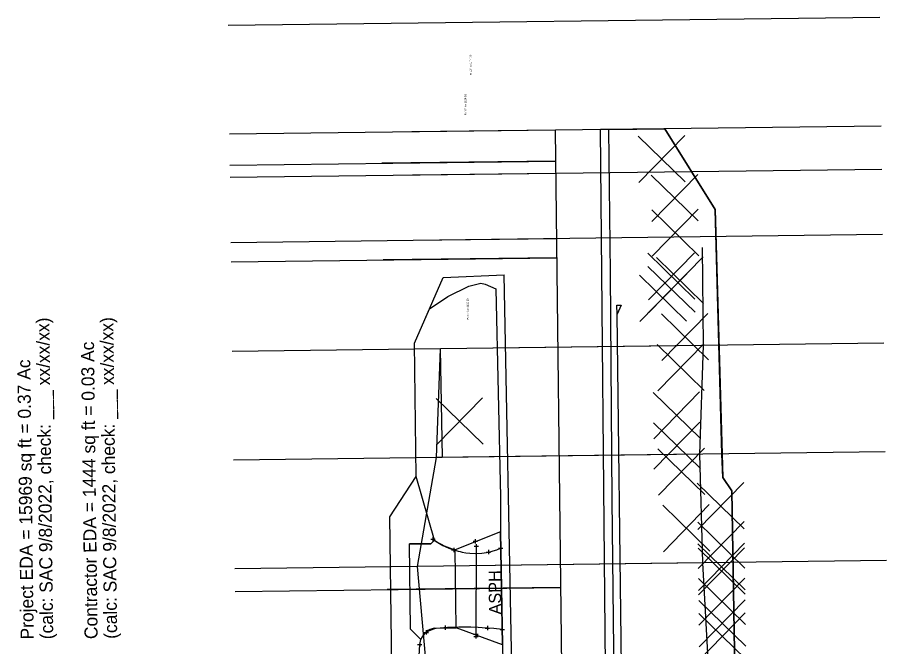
# Model space of a CAD drawing. Extents: x 2341000 to 2341204, y 624110 to 624511.
# Drawn here: x 2341000.5 to 2341200.5, y 624366.6 to 624511.4 of the extents above; entities that cross this region are included whole.
import ezdxf

# ---------------------------------------------------------------- set-up
doc = ezdxf.new("R2010")
doc.units = 0
for name, color, linetype in [('DR_X_Elev_Flow', 7, 'Continuous'), ('DR_X_Storm_Sewer', 7, 'Continuous'), ('GE_P_Driveway_CL', 7, 'Continuous'), ('PV_P_Drive', 7, 'Continuous'), ('PV_X_Text', 7, 'Continuous'), ('RD_P_GR_Rt', 7, 'Continuous'), ('RW_P_Const_Limits', 7, 'Continuous'), ('SC_ProfileRun1', 7, 'Continuous'), ('SC_Scratch1', 7, 'Continuous'), ('SC_Scratch10', 7, 'Continuous'), ('SC_Scratch2', 7, 'Continuous'), ('SC_Scratch4', 7, 'Continuous'), ('SC_Scratch5', 7, 'Continuous'), ('SV_X_Shot_Marker', 7, 'Continuous'), ('VG_P_Cells', 7, 'Continuous')]:
    doc.layers.add(name, color=color, linetype=linetype)

msp = doc.modelspace()

# ---------------------------------------------------------------- linework, layer by layer
at = {"layer": 'DR_X_Elev_Flow'}
for p, q in [((2341106.04, 624390.2), (2341106.04, 624389.2)), ((2341105.54, 624389.7), (2341106.54, 624389.7)), ((2341106.04, 624389.7), (2341106.04, 624389.7)), ((2341105.96, 624369.99), (2341105.96, 624368.99)), ((2341105.46, 624369.49), (2341106.46, 624369.49)), ((2341105.96, 624369.49), (2341105.96, 624369.49))]:
    msp.add_line(p, q, dxfattribs=at)
at = {"layer": 'DR_X_Storm_Sewer'}
for p, q in [((2341106.04, 624389.7), (2341105.96, 624369.49)), ((2341106.04, 624389.7), (2341105.96, 624369.49)), ((2341106.04, 624389.7), (2341106.04, 624389.7)), ((2341105.96, 624369.49), (2341105.96, 624369.49))]:
    msp.add_line(p, q, dxfattribs=at)
at = {"layer": 'GE_P_Driveway_CL'}
msp.add_line((2341125.56, 624380.22), (2341085.56, 624379.72), dxfattribs=at)
at = {"layer": 'PV_P_Drive'}
for p, q in [((2341111.66, 624393.04), (2341101.18, 624388.91)), ((2341111.66, 624393.04), (2341101.18, 624388.91)), ((2341095.6, 624390.28), (2341090.68, 624390.22)), ((2341095.6, 624390.28), (2341090.68, 624390.22)), ((2341090.92, 624370.6), (2341090.68, 624390.22)), ((2341090.92, 624370.6), (2341090.68, 624390.22)), ((2341096.41, 624391.11), (2341095.6, 624390.28)), ((2341096.41, 624391.11), (2341095.6, 624390.28)), ((2341101.4, 624370.92), (2341101.18, 624388.91)), ((2341101.4, 624370.92), (2341101.18, 624388.91)), ((2341093.32, 624368.26), (2341090.92, 624370.6)), ((2341093.32, 624368.26), (2341090.92, 624370.6)), ((2341096.4, 624370.85), (2341101.4, 624370.92)), ((2341096.4, 624370.85), (2341101.4, 624370.92)), ((2341112.12, 624367.05), (2341101.4, 624370.92)), ((2341112.12, 624367.05), (2341101.4, 624370.92))]:
    msp.add_line(p, q, dxfattribs=at)
msp.add_lwpolyline([(2341112.12, 624367.05), (2341111.86, 624380.05), (2341111.66, 624393.04)], dxfattribs=at)
msp.add_lwpolyline([(2341112.12, 624367.05), (2341111.86, 624380.05), (2341111.66, 624393.04)], dxfattribs=at)
for centre, radius, start, end in [((2341104.98, 624403.43), 15, 235.168, 255.3249), ((2341104.98, 624403.43), 15, 235.168, 255.3249), ((2341097.09, 624366.91), 4, 99.9333, 160.2994), ((2341097.09, 624366.91), 4, 99.9333, 160.2994)]:
    msp.add_arc(centre, radius, start, end, dxfattribs=at)
at = {"layer": 'RD_P_GR_Rt'}
for p, q in [((2341138.44, 624445.13), (2341139.44, 624445.14)), ((2341138.46, 624443.13), (2341138.44, 624445.13)), ((2341139.44, 624445.14), (2341138.46, 624443.13)), ((2341140.75, 624255.64), (2341138.46, 624443.13))]:
    msp.add_line(p, q, dxfattribs=at)
at = {"layer": 'RW_P_Const_Limits'}
for p, q in [((2341149.46, 624485.77), (2341134.66, 624485.59)), ((2341135.83, 624358.38), (2341134.66, 624485.59)), ((2341161.03, 624467.15), (2341149.46, 624485.77)), ((2341162.54, 624410.92), (2341161.03, 624467.15)), ((2341114.29, 624358.12), (2341112.45, 624452.18)), ((2341086.19, 624396.46), (2341092.24, 624405.75)), ((2341086.67, 624357.74), (2341086.19, 624396.46))]:
    msp.add_line(p, q, dxfattribs=at)
for points in [[(2341092.24, 624405.75), (2341091.86, 624436.46), (2341098.43, 624451.53), (2341112.45, 624452.18)], [(2341165.58, 624360.98), (2341164.88, 624402.48), (2341162.81, 624405.53), (2341162.54, 624410.92)]]:
    msp.add_lwpolyline(points, dxfattribs=at)
at = {"layer": 'SC_ProfileRun1'}
msp.add_line((2341106.04, 624389.7), (2341105.96, 624369.49), dxfattribs=at)
at = {"layer": 'SC_Scratch1'}
for p, q in [((2341198.95, 624511.38), (2341048.96, 624509.53)), ((2341199.25, 624486.38), (2341049.27, 624484.53)), ((2341049.35, 624477.38), (2341124.35, 624478.3)), ((2341199.38, 624476.38), (2341049.39, 624474.53)), ((2341199.56, 624461.39), (2341049.57, 624459.53)), ((2341049.63, 624455.15), (2341124.62, 624456.08)), ((2341199.87, 624436.39), (2341049.88, 624434.53)), ((2341200.18, 624411.39), (2341050.19, 624409.54)), ((2341200.49, 624386.39), (2341050.5, 624384.54)), ((2341050.57, 624379.29), (2341125.56, 624380.22))]:
    msp.add_line(p, q, dxfattribs=at)
at = {"layer": 'SC_Scratch10'}
for points in [[(2341138.01, 624338.62), (2341137.31, 624400.34), (2341136.96, 624452.62), (2341136.56, 624485.61), (2341149.46, 624485.77), (2341161.03, 624467.15), (2341162.81, 624405.53), (2341164.88, 624402.48), (2341165.58, 624360.98)], [(2341092.56, 624357.81), (2341093.07, 624367.11), (2341093.32, 624368.26), (2341090.92, 624370.6), (2341090.68, 624390.22), (2341095.6, 624390.28), (2341096.41, 624391.11), (2341092.24, 624405.75), (2341091.86, 624436.46), (2341095.32, 624444.36), (2341099.55, 624447.14), (2341104.32, 624449.54), (2341107.09, 624450.21), (2341108.13, 624449.98), (2341110.6, 624448.93), (2341111.64, 624401.06), (2341111.66, 624393.04), (2341112.12, 624367.05), (2341112.63, 624338.3)]]:
    msp.add_lwpolyline(points, dxfattribs=at)
at = {"layer": 'SC_Scratch2'}
for p, q in [((2341124.26, 624485.46), (2341091.26, 624485.05)), ((2341128.28, 624160.48), (2341124.26, 624485.46)), ((2341124.38, 624475.46), (2341091.39, 624475.05)), ((2341124.57, 624460.46), (2341091.57, 624460.05)), ((2341158.38, 624435.87), (2341097.8, 624435.13)), ((2341098.29, 624410.13), (2341097.8, 624435.13)), ((2341157.54, 624410.86), (2341096.91, 624410.11)), ((2341158.21, 624385.87), (2341092.5, 624385.06))]:
    msp.add_line(p, q, dxfattribs=at)
for points in [[(2341155.11, 624260.82), (2341157.95, 624285.86), (2341158.38, 624298.86), (2341164.96, 624309.95), (2341158.94, 624318.87), (2341165.58, 624327.96), (2341162.38, 624338.92), (2341159.54, 624360.88), (2341158.21, 624385.87), (2341157.54, 624410.86), (2341158.38, 624435.87), (2341158.1, 624458.4)], [(2341100.88, 624160.14), (2341094.03, 624185.06), (2341090.66, 624210.02), (2341083.8, 624234.94), (2341083.68, 624259.94), (2341082.07, 624284.92), (2341082.17, 624297.92), (2341086.01, 624308.97), (2341075.63, 624317.84), (2341092.17, 624327.05), (2341094.86, 624338.08), (2341094.77, 624360.08), (2341092.5, 624385.06), (2341096.91, 624410.11), (2341097.8, 624435.13)], [(2341155.11, 624260.82), (2341157.95, 624285.86), (2341158.38, 624298.86), (2341164.96, 624309.95), (2341158.94, 624318.87), (2341165.58, 624327.96), (2341162.38, 624338.92), (2341159.54, 624360.88), (2341158.21, 624385.87), (2341157.54, 624410.86), (2341158.38, 624435.87)]]:
    msp.add_lwpolyline(points, dxfattribs=at)
at = {"layer": 'SC_Scratch4'}
for p, q in [((2341124.35, 624478.3), (2341084.35, 624477.81)), ((2341124.62, 624456.08), (2341084.63, 624455.58))]:
    msp.add_line(p, q, dxfattribs=at)
at = {"layer": 'SC_Scratch5'}
msp.add_lwpolyline([(2341112.05, 624370.55), (2341110.12, 624370.76), (2341108.63, 624370.88), (2341107.43, 624370.96), (2341106.53, 624371), (2341104.83, 624371.05), (2341102.01, 624371.06), (2341099.46, 624370.97), (2341098.61, 624370.92), (2341097.78, 624370.86), (2341096.84, 624370.74), (2341096.25, 624370.62), (2341095.57, 624370.41), (2341094.93, 624370.12), (2341094.45, 624369.8), (2341094.08, 624369.47), (2341093.76, 624369.09), (2341093.44, 624368.57), (2341093.32, 624368.26), (2341090.92, 624370.6), (2341090.68, 624390.22), (2341095.6, 624390.28), (2341096.41, 624391.11), (2341096.59, 624390.97), (2341097.18, 624390.56), (2341098.36, 624389.88), (2341099.08, 624389.54), (2341099.74, 624389.27), (2341100.69, 624388.93), (2341100.95, 624388.84), (2341101.42, 624388.7), (2341101.89, 624388.58), (2341102.32, 624388.48), (2341102.85, 624388.36), (2341103.68, 624388.22), (2341104.55, 624388.12), (2341105.8, 624388.05), (2341107.33, 624388.11), (2341108.44, 624388.26), (2341109.23, 624388.43), (2341109.97, 624388.63), (2341110.76, 624388.9), (2341111.67, 624389.28)], close=True, dxfattribs=at)
at = {"layer": 'SV_X_Shot_Marker'}
for p, q in [((2341095.59, 624391.35), (2341096.59, 624391.35)), ((2341096.09, 624391.85), (2341096.09, 624390.85)), ((2341096.09, 624391.35), (2341096.09, 624391.35)), ((2341105.34, 624390.83), (2341106.34, 624390.83)), ((2341105.84, 624391.33), (2341105.84, 624390.33)), ((2341105.84, 624390.83), (2341105.84, 624390.83)), ((2341100.36, 624388.87), (2341101.36, 624388.87)), ((2341100.86, 624389.37), (2341100.86, 624388.37)), ((2341100.86, 624388.87), (2341100.86, 624388.87)), ((2341108.34, 624388.34), (2341109.34, 624388.34)), ((2341108.84, 624388.84), (2341108.84, 624387.84)), ((2341108.84, 624388.34), (2341108.84, 624388.34)), ((2341111.17, 624389.28), (2341112.17, 624389.28)), ((2341111.67, 624389.78), (2341111.67, 624388.78)), ((2341111.67, 624389.28), (2341111.67, 624389.28)), ((2341094.54, 624370.37), (2341094.54, 624369.37)), ((2341098.41, 624370.94), (2341099.41, 624370.94)), ((2341098.91, 624371.44), (2341098.91, 624370.44)), ((2341098.91, 624370.94), (2341098.91, 624370.94)), ((2341108.13, 624370.88), (2341109.13, 624370.88)), ((2341108.63, 624371.38), (2341108.63, 624370.38)), ((2341108.63, 624370.88), (2341108.63, 624370.88)), ((2341111.55, 624370.55), (2341112.55, 624370.55)), ((2341112.05, 624371.05), (2341112.05, 624370.05)), ((2341112.05, 624370.55), (2341112.05, 624370.55)), ((2341094.04, 624369.87), (2341095.04, 624369.87)), ((2341094.54, 624369.87), (2341094.54, 624369.87)), ((2341105.48, 624368.97), (2341106.48, 624368.97)), ((2341105.98, 624369.47), (2341105.98, 624368.47)), ((2341105.98, 624368.97), (2341105.98, 624368.97)), ((2341092.57, 624367.11), (2341093.57, 624367.11)), ((2341093.07, 624367.61), (2341093.07, 624366.61)), ((2341093.07, 624367.11), (2341093.07, 624367.11))]:
    msp.add_line(p, q, dxfattribs=at)
at = {"layer": 'VG_P_Cells'}
for p, q in [((2341143.33, 624484.08), (2341154.15, 624473.52)), ((2341143.46, 624473.39), (2341154.02, 624484.22)), ((2341148.74, 624478.8), (2341148.74, 624478.8)), ((2341146.34, 624475.11), (2341157.16, 624464.55)), ((2341146.47, 624464.42), (2341157.03, 624475.25)), ((2341151.75, 624469.83), (2341151.75, 624469.83)), ((2341146.44, 624467.11), (2341157.26, 624456.55)), ((2341146.57, 624456.42), (2341157.13, 624467.25)), ((2341151.85, 624461.83), (2341151.85, 624461.83)), ((2341145.55, 624457.1), (2341156.38, 624446.54)), ((2341145.69, 624446.41), (2341156.25, 624457.23)), ((2341147.56, 624456.13), (2341158.38, 624445.57)), ((2341147.69, 624445.44), (2341158.25, 624456.26)), ((2341145.57, 624454.1), (2341156.4, 624443.54)), ((2341145.71, 624443.41), (2341156.27, 624454.23)), ((2341143.59, 624452.08), (2341154.41, 624441.52)), ((2341143.72, 624441.39), (2341154.28, 624452.21)), ((2341150.97, 624451.82), (2341150.97, 624451.82)), ((2341152.97, 624450.85), (2341152.97, 624450.85)), ((2341150.99, 624448.82), (2341150.99, 624448.82)), ((2341149, 624446.8), (2341149, 624446.8)), ((2341148.65, 624443.14), (2341159.47, 624432.58)), ((2341148.78, 624432.45), (2341159.34, 624443.27)), ((2341147.7, 624436.13), (2341158.52, 624425.57)), ((2341147.83, 624425.44), (2341158.39, 624436.26)), ((2341154.06, 624437.86), (2341154.06, 624437.86)), ((2341153.11, 624430.85), (2341153.11, 624430.85)), ((2341146.77, 624425.11), (2341157.59, 624414.56)), ((2341146.9, 624414.42), (2341157.46, 624425.25)), ((2341096.81, 624423.71), (2341107.63, 624413.15)), ((2341096.94, 624413.02), (2341107.5, 624423.84)), ((2341102.22, 624418.43), (2341102.22, 624418.43)), ((2341146.82, 624418.11), (2341157.64, 624407.56)), ((2341146.95, 624407.42), (2341157.51, 624418.25)), ((2341152.18, 624419.83), (2341152.18, 624419.83)), ((2341147.86, 624412.13), (2341158.68, 624401.57)), ((2341147.99, 624401.44), (2341158.55, 624412.26)), ((2341152.23, 624412.83), (2341152.23, 624412.83)), ((2341153.27, 624406.85), (2341153.27, 624406.85)), ((2341156.92, 624404.24), (2341167.74, 624393.68)), ((2341157.05, 624393.55), (2341167.61, 624404.37)), ((2341148.98, 624399.14), (2341159.8, 624388.58)), ((2341149.11, 624388.45), (2341159.67, 624399.27)), ((2341162.33, 624398.96), (2341162.33, 624398.96)), ((2341157.02, 624395.24), (2341167.85, 624384.68)), ((2341157.16, 624384.55), (2341167.72, 624395.37)), ((2341154.39, 624393.86), (2341154.39, 624393.86)), ((2341157.08, 624390.24), (2341167.91, 624379.68)), ((2341157.22, 624379.55), (2341167.77, 624390.37)), ((2341162.43, 624389.96), (2341162.43, 624389.96)), ((2341157.1, 624389.24), (2341167.92, 624378.68)), ((2341157.23, 624378.55), (2341167.79, 624389.37)), ((2341162.49, 624384.96), (2341162.49, 624384.96)), ((2341162.51, 624383.96), (2341162.51, 624383.96)), ((2341157.18, 624382.24), (2341168, 624371.68)), ((2341157.31, 624371.55), (2341167.87, 624382.37)), ((2341157.24, 624377.24), (2341168.06, 624366.68)), ((2341157.37, 624366.55), (2341167.93, 624377.37)), ((2341162.59, 624376.96), (2341162.59, 624376.96)), ((2341157.27, 624374.24), (2341168.1, 624363.68)), ((2341157.41, 624363.55), (2341167.96, 624374.37)), ((2341162.65, 624371.96), (2341162.65, 624371.96)), ((2341162.68, 624368.96), (2341162.68, 624368.96))]:
    msp.add_line(p, q, dxfattribs=at)

# ---------------------------------------------------------------- texts
at = {"layer": 'PV_X_Text'}
msp.add_text('ASPH', height=2.8, rotation=90.7192, dxfattribs=at).set_placement((2341111.81, 624374.01))
at = {"layer": 'SC_Scratch1'}
for s, p in [('Pr 12" inv 1124.30', (2341105, 624498.08)), ('Ex 12" inv 1124.01', (2341103.81, 624488.89)), ('Ex 12" inv 1122.29', (2341104.34, 624441.89))]:
    msp.add_text(s, height=0.4167, rotation=90.7079, dxfattribs=at).set_placement(p)
at = {"layer": 'SC_Scratch10'}
for s, p in [('(calc: SAC 9/8/2022, check: ___ xx/xx/xx)', (2341008.72, 624368.32)), ('(calc: SAC 9/8/2022, check: ___ xx/xx/xx)', (2341023.43, 624368.41)), ('Contractor EDA = 1444 sq ft = 0.03 Ac', (2341018.93, 624368.35)), ('Project EDA = 15969 sq ft = 0.37 Ac', (2341004.22, 624368.26))]:
    msp.add_text(s, height=3, rotation=90.7079, dxfattribs=at).set_placement(p)

doc.saveas('drawing.dxf')
